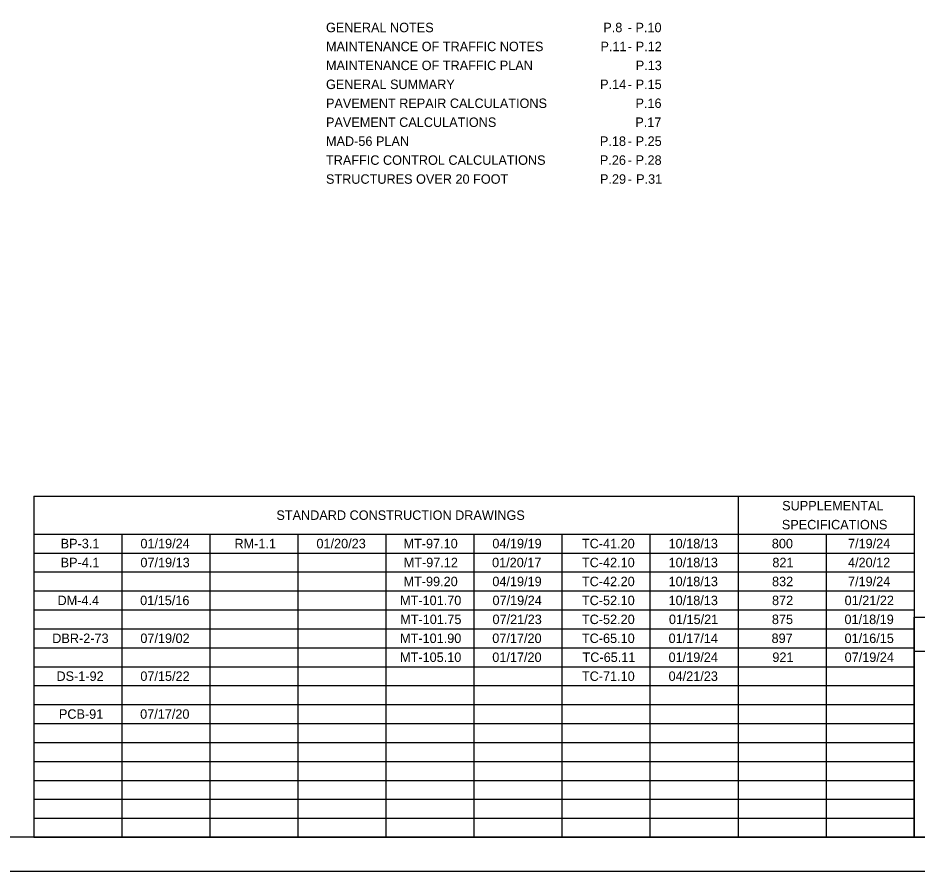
# Model space of a CAD drawing. Extents: x 0 to 36.5, y 0 to 25.3.
# Drawn here: x 10.01 to 23.3, y 0 to 12.61 of the extents above; entities that cross this region are included whole.
import ezdxf

# ---------------------------------------------------------------- set-up
doc = ezdxf.new("R2010")
doc.units = 0
for name, color, linetype in [('GM_X_Minor_River', 7, 'Continuous'), ('SH_Border', 7, 'Continuous'), ('SH_Cut_Line', 7, 'Continuous'), ('SH_Data', 7, 'Continuous'), ('SH_Text', 7, 'Continuous')]:
    doc.layers.add(name, color=color, linetype=linetype)

msp = doc.modelspace()

# ---------------------------------------------------------------- linework, layer by layer
at = {"layer": 'SH_Border'}
msp.add_lwpolyline([(1.5, 21.5), (33.5, 21.5), (33.5, 0.5), (1.5, 0.5)], close=True, dxfattribs=at)
at = {"layer": 'SH_Cut_Line'}
msp.add_lwpolyline([(0, 0), (34, 0), (34, 22), (0, 22)], close=True, dxfattribs=at)
at = {"layer": 'SH_Data'}
for p, q in [((23.256, 0.5), (23.256, 3.75)), ((23.256, 3.75), (26.056, 3.75)), ((23.256, 3.25), (26.056, 3.25)), ((23.256, 0.5), (26.056, 0.5))]:
    msp.add_line(p, q, dxfattribs=at)
at = {"layer": 'SH_Text'}
for p, q in [((10.244, 5.54), (23.256, 5.54)), ((10.244, 5.54), (10.244, 0.5)), ((20.654, 5.54), (20.654, 0.5)), ((23.256, 5.54), (23.256, 0.5)), ((10.244, 4.98), (23.256, 4.98)), ((11.545, 4.98), (11.545, 0.5)), ((12.846, 4.98), (12.846, 0.5)), ((14.148, 4.98), (14.148, 0.5)), ((15.449, 4.98), (15.449, 0.5)), ((16.75, 4.98), (16.75, 0.5)), ((18.051, 4.98), (18.051, 0.5)), ((19.352, 4.98), (19.352, 0.5)), ((21.955, 4.98), (21.955, 0.5)), ((10.244, 4.7), (23.256, 4.7)), ((10.244, 4.42), (23.256, 4.42)), ((10.244, 4.14), (23.256, 4.14)), ((10.244, 3.86), (23.256, 3.86)), ((10.244, 3.58), (23.256, 3.58)), ((10.244, 3.3), (23.256, 3.3)), ((10.244, 3.02), (23.256, 3.02)), ((10.244, 2.74), (23.256, 2.74)), ((10.244, 2.46), (23.256, 2.46)), ((10.244, 2.18), (23.256, 2.18)), ((10.244, 1.9), (23.256, 1.9)), ((10.244, 1.62), (23.256, 1.62)), ((10.244, 1.34), (23.256, 1.34)), ((10.244, 1.06), (23.256, 1.06)), ((10.244, 0.78), (23.256, 0.78)), ((10.244, 0.5), (23.256, 0.5))]:
    msp.add_line(p, q, dxfattribs=at)

# ---------------------------------------------------------------- texts
at = {"layer": 'GM_X_Minor_River'}
for s, p in [('GENERAL NOTES', (14.564, 12.398)), ('P.8', (18.663, 12.398)), ('P.10', (19.139, 12.398)), ('-', (19.025, 12.398)), ('MAINTENANCE OF TRAFFIC NOTES', (14.564, 12.118)), ('P.11', (18.621, 12.118)), ('P.12', (19.142, 12.118)), ('-', (19.025, 12.118)), ('MAINTENANCE OF TRAFFIC PLAN', (14.564, 11.838)), ('P.13', (19.143, 11.838)), ('GENERAL SUMMARY', (14.564, 11.558)), ('P.14', (18.616, 11.558)), ('P.15', (19.141, 11.558)), ('-', (19.025, 11.558)), ('PAVEMENT REPAIR CALCULATIONS', (14.564, 11.278)), ('P.16', (19.139, 11.278)), ('PAVEMENT CALCULATIONS', (14.564, 10.998)), ('P.17', (19.136, 10.998)), ('MAD-56 PLAN', (14.564, 10.718)), ('P.18', (18.613, 10.718)), ('-', (19.025, 10.718)), ('P.25', (19.141, 10.718)), ('TRAFFIC CONTROL CALCULATIONS', (14.564, 10.438)), ('P.26', (18.612, 10.438)), ('-', (19.025, 10.438)), ('P.28', (19.14, 10.438)), ('STRUCTURES OVER 20 FOOT', (14.564, 10.158)), ('P.29', (18.614, 10.158)), ('P.31', (19.148, 10.158)), ('-', (19.025, 10.158))]:
    msp.add_text(s, height=0.14, dxfattribs=at).set_placement(p)
at = {"layer": 'SH_Text'}
for s, p in [('SUPPLEMENTAL', (21.307, 5.33)), ('STANDARD CONSTRUCTION DRAWINGS', (13.831, 5.19)), ('SPECIFICATIONS', (21.302, 5.05)), ('01/19/24', (11.821, 4.77)), ('01/20/23', (14.423, 4.77)), ('04/19/19', (17.023, 4.77)), ('10/18/13', (19.628, 4.77)), ('7/19/24', (22.28, 4.77)), ('BP-3.1', (10.642, 4.77)), ('RM-1.1', (13.211, 4.77)), ('MT-97.10', (15.71, 4.77)), ('TC-41.20', (18.347, 4.77)), ('800', (21.154, 4.77)), ('BP-4.1', (10.642, 4.49)), ('07/19/13', (11.821, 4.49)), ('MT-97.12', (15.713, 4.49)), ('01/20/17', (17.019, 4.49)), ('TC-42.10', (18.347, 4.49)), ('10/18/13', (19.628, 4.49)), ('821', (21.162, 4.49)), ('4/20/12', (22.28, 4.49)), ('MT-99.20', (15.71, 4.21)), ('04/19/19', (17.023, 4.21)), ('TC-42.20', (18.347, 4.21)), ('10/18/13', (19.628, 4.21)), ('832', (21.157, 4.21)), ('7/19/24', (22.28, 4.21)), ('DM-4.4', (10.596, 3.93)), ('01/15/16', (11.817, 3.93)), ('MT-101.70', (15.659, 3.93)), ('07/19/24', (17.025, 3.93)), ('TC-52.10', (18.347, 3.93)), ('10/18/13', (19.628, 3.93)), ('872', (21.157, 3.93)), ('01/21/22', (22.23, 3.93)), ('MT-101.75', (15.661, 3.65)), ('07/21/23', (17.025, 3.65)), ('TC-52.20', (18.347, 3.65)), ('01/15/21', (19.633, 3.65)), ('875', (21.155, 3.65)), ('01/18/19', (22.228, 3.65)), ('DBR-2-73', (10.518, 3.37)), ('07/19/02', (11.82, 3.37)), ('MT-101.90', (15.659, 3.37)), ('07/17/20', (17.022, 3.37)), ('TC-65.10', (18.347, 3.37)), ('01/17/14', (19.628, 3.37)), ('897', (21.15, 3.37)), ('01/16/15', (22.229, 3.37)), ('MT-105.10', (15.659, 3.09)), ('01/17/20', (17.022, 3.09)), ('TC-65.11', (18.356, 3.09)), ('01/19/24', (19.628, 3.09)), ('921', (21.162, 3.09)), ('07/19/24', (22.23, 3.09)), ('DS-1-92', (10.58, 2.81)), ('07/15/22', (11.82, 2.81)), ('TC-71.10', (18.347, 2.81)), ('04/21/23', (19.628, 2.81)), ('PCB-91', (10.616, 2.25)), ('07/17/20', (11.817, 2.25))]:
    msp.add_text(s, height=0.14, dxfattribs=at).set_placement(p)

doc.saveas('drawing.dxf')
